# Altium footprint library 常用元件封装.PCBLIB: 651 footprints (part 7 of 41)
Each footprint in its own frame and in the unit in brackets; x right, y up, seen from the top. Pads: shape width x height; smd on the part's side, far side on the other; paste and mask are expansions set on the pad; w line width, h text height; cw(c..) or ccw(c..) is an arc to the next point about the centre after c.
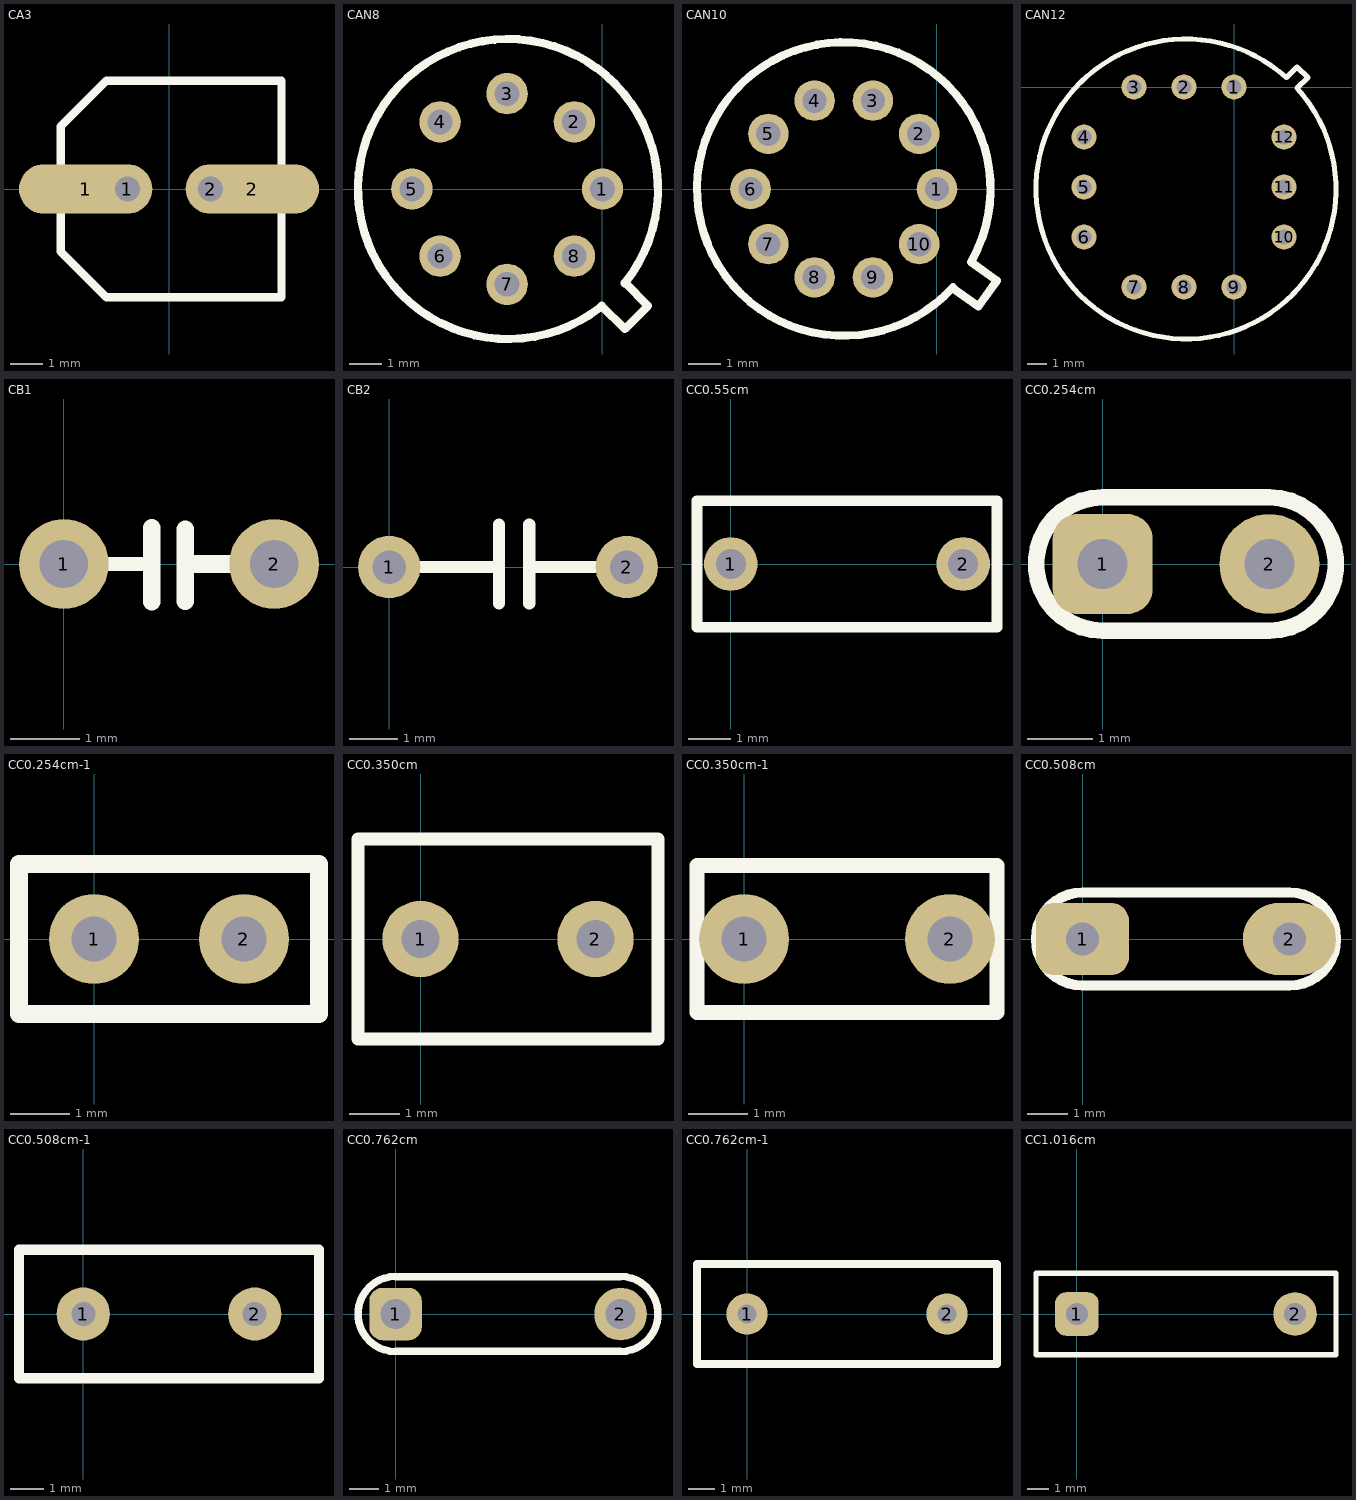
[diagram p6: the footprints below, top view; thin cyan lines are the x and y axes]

## CA3 [mm] "直径6.4mm孔距2.54mm"
pads (4):
  oval 4.064x1.5 smd: 1(-2.54,0) 2(2.54,0)
  round 1.5 hole 0.762: 1(-1.27,0) 2(1.27,0)
TopOverlay:
  lines w0.254: -3.302,-0.762 -3.302,-1.905 -1.905,-3.302 3.429,-3.302 3.429,-0.762 ; -3.302,0.762 -3.302,1.905 -1.905,3.302 3.429,3.302 3.429,0.762

## CAN8 [mil]
pads (8):
  round 50 hole 30: 1(0,0) 2(-34,81) 3(-115,115) 4(-196,81) 5(-230,0) 6(-196,-81) 7(-115,-115) 8(-34,-81)
TopOverlay:
  lines w10: -2.57,-142.63 cw(c-114,0) 26.66,-113.91 ; -1,-141 27,-169 55,-141 27,-113

## CAN10 [mil]
pads (10):
  round 50 hole 30: 1(0,0) 2(-22,68) 3(-79,109) 4(-151,109) 5(-208,68) 6(-230,0) 7(-208,-68) 8(-151,-109) 9(-79,-109) 10(-22,-68)
TopOverlay:
  lines w10: 19,-122 51,-145 74,-113 42,-90 ; 19.51,-121.11 cw(c-115,0) 43.31,-87.75

## CAN12 [mil]
pads (12):
  round 50 hole 30: 1(0,0) 2(-100,0) 3(-200,0) 4(-300,-100) 5(-300,-200) 6(-300,-300) 7(-200,-400) 8(-100,-400) 9(0,-400) 10(100,-300) 11(100,-200) 12(100,-100)
TopOverlay:
  lines w10: 104.74,18.94 ccw(c-96,-204) 126.94,-3.26 ; 105,19 126,40 148,19 126,-2

## CB1 [mm]
pads (2):
  round 1.3 hole 0.7: 1(0,0) 2(3.048,0)
TopOverlay:
  lines w0.203: 0,0 1.143,0
  lines w0.254: 1.271,0.522 1.272,-0.546 ; 1.757,-0.54 1.757,0.504 ; 1.778,0 3.048,0

## CB2 [mm]
pads (2):
  round 1.3 hole 0.7: 1(0,0) 2(4.953,0)
TopOverlay:
  lines w0.254: 0.635,0 1.27,0 2.286,0 ; 2.286,-0.762 2.286,0.889 ; 2.921,-0.762 2.921,0.889 ; 3.048,0 4.953,0

## CC0.55cm [mil] "5.5mm"
pads (2):
  round 50 hole 28: 1(0,0) 2(216.53,0)
TopOverlay:
  lines w10: -31.5,-59.05 -31.5,59.05 248.03,59.05 248.03,-59.05 -31.5,-59.05

## CC0.254cm [mil] "4.57mm2.54mm"
pads (2):
  rrect50% 60x60 hole 30: 1(0,0)
  round 60 hole 30: 2(100,0)
TopOverlay:
  lines w10: 0,-40 cw(c0,0) 0,40 100,40 cw(c100,0) 100,-40 0,-40

## CC0.254cm-1 [mil] "5.08mm2.54mm"
pads (2):
  round 60 hole 30: 1(0,0) 2(100,0)
TopOverlay:
  lines w12: -50,-50 150,-50 150,50 -50,50 -50,-50

## CC0.350cm [mil] "6mm3.5mm"
pads (2):
  round 60 hole 30: 1(0,0) 2(137.79,0)
TopOverlay:
  lines w10: -49.21,-78.74 187.01,-78.74 187.01,78.74 -49.21,78.74 -49.21,-78.74

## CC0.350cm-1 [mil] "5.2mm"
pads (2):
  round 60 hole 30: 1(0,0) 2(137.79,0)
TopOverlay:
  lines w10: -31.5,-49.21 169.29,-49.21 169.29,49.21 -31.5,49.21 -31.5,-49.21

## CC0.508cm [mil] "5.08mm"
pads (2):
  rrect50% 90x70 hole 32: 1(0,0)
  oval 90x70 hole 32: 2(200,0)
TopOverlay:
  lines w10: 0,-45 cw(c0,0) 0,45 200,45 cw(c200,0) 200,-45 0,-45

## CC0.508cm-1 [mil]
pads (2):
  round 62 hole 28: 1(0,0) 2(200,0)
TopOverlay:
  lines w12: -75,-75 275,-75 275,75 -75,75 -75,-75

## CC0.762cm [mil] "7.62mm"
pads (2):
  rrect50% 70x70 hole 40: 1(0,0)
  round 70 hole 40: 2(300,0)
TopOverlay:
  lines w10: 0,-50 cw(c0,0) 0,50 300,50 cw(c300,0) 300,-50 0,-50

## CC0.762cm-1 [mil]
pads (2):
  round 62 hole 28: 1(0,0) 2(300,0)
TopOverlay:
  lines w12: -75,-75 -75,75 375,75 375,-75 -75,-75

## CC1.016cm [mil] "10.16mm"
pads (2):
  rrect50% 80x80 hole 40: 1(0,0)
  round 80 hole 40: 2(400,0)
TopOverlay:
  lines w10: -75,-75 0,-75 400,-75 475,-75 475,75 400,75 0,75 -75,75 -75,-75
